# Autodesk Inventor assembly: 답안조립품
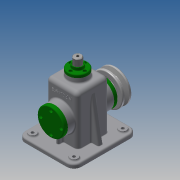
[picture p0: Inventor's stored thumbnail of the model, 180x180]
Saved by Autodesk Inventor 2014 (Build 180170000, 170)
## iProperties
Created: 2015-12
Part Number: 답안조립품
Document SubType Name: Assembly
Designer: Administrator
Author: Administrator
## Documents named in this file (17)
- D:\451225V1021\답안조립품.iam
- D:\451225V1021\1-본체.ipt
- D:\451225V1021\베어링 15 x 35 x 11.ipt
- D:\451225V1021\앞커버.ipt
- D:\451225V1021\뒤커버.ipt
- D:\451225V1021\오일실 15 25 7.ipt
- D:\451225V1021\상부부시.ipt
- D:\451225V1021\와셔.ipt
- D:\451225V1021\멈춤링 15 x 1.ipt
- D:\451225V1021\편심축.ipt
- D:\451225V1021\V-벨트풀리.ipt
- D:\451225V1021\키 5 x 5 x 14.ipt
- D:\451225V1021\고정핀.ipt
- D:\451225V1021\링크.ipt
- D:\451225V1021\슬라이드바.ipt
- D:\451225V1021\멈춤링 6 x 5.ipt
- D:\451225V1021\볼트 M6 x 12.ipt
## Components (4 placed, 4 different names)
1. 1-본체:1
2. V-벨트풀리:1
3. 고정핀:1
4. ISO 4018 M6 x 12:1
